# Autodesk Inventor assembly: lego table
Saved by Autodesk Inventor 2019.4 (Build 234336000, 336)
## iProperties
Created: 2020-09
Part Number: lego table
Document SubType Name: Assembly
Designer: Administrator
Title: lego table v49
Author: Administrator
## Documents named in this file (20)
- c:\worker\convert-fusion-r07\tmp\job-1\164\output\files\c50c4620-2026-4653-9277-f8972be5ac5a\c5b1a24b-4982-40ab-9d19-aea12fee247f.iam
- c:\worker\convert-fusion-r07\tmp\job-1\164\output\files\c50c4620-2026-4653-9277-f8972be5ac5a\back.ipt
- c:\worker\convert-fusion-r07\tmp\job-1\164\output\files\c50c4620-2026-4653-9277-f8972be5ac5a\side.ipt
- c:\worker\convert-fusion-r07\tmp\job-1\164\output\files\c50c4620-2026-4653-9277-f8972be5ac5a\front.ipt
- c:\worker\convert-fusion-r07\tmp\job-1\164\output\files\c50c4620-2026-4653-9277-f8972be5ac5a\front trim.ipt
- c:\worker\convert-fusion-r07\tmp\job-1\164\output\files\c50c4620-2026-4653-9277-f8972be5ac5a\bottom insert.ipt
- c:\worker\convert-fusion-r07\tmp\job-1\164\output\files\c50c4620-2026-4653-9277-f8972be5ac5a\rail support.ipt
- c:\worker\convert-fusion-r07\tmp\job-1\164\output\files\c50c4620-2026-4653-9277-f8972be5ac5a\leg.iam
- c:\worker\convert-fusion-r07\tmp\job-1\164\output\files\c50c4620-2026-4653-9277-f8972be5ac5a\leg_1.iam
- c:\worker\convert-fusion-r07\tmp\job-1\164\output\files\c50c4620-2026-4653-9277-f8972be5ac5a\leg_2.iam
- c:\worker\convert-fusion-r07\tmp\job-1\164\output\files\c50c4620-2026-4653-9277-f8972be5ac5a\leg_3.iam
- c:\worker\convert-fusion-r07\tmp\job-1\164\output\files\c50c4620-2026-4653-9277-f8972be5ac5a\roller shelf v31.iam
- c:\worker\convert-fusion-r07\tmp\job-1\164\output\files\c50c4620-2026-4653-9277-f8972be5ac5a\base stiffener.ipt
- c:\worker\convert-fusion-r07\tmp\job-1\164\output\files\c50c4620-2026-4653-9277-f8972be5ac5a\divider.ipt
- c:\worker\convert-fusion-r07\tmp\job-1\164\output\files\c50c4620-2026-4653-9277-f8972be5ac5a\shelf leg a.ipt
- c:\worker\convert-fusion-r07\tmp\job-1\164\output\files\c50c4620-2026-4653-9277-f8972be5ac5a\shelf leg b.ipt
- c:\worker\convert-fusion-r07\tmp\job-1\164\output\files\c50c4620-2026-4653-9277-f8972be5ac5a\shelf.ipt
- c:\worker\convert-fusion-r07\tmp\job-1\164\output\files\c50c4620-2026-4653-9277-f8972be5ac5a\shelf trim.ipt
- c:\worker\convert-fusion-r07\tmp\job-1\164\output\files\c50c4620-2026-4653-9277-f8972be5ac5a\shelf backing.ipt
- c:\worker\convert-fusion-r07\tmp\job-1\164\output\files\c50c4620-2026-4653-9277-f8972be5ac5a\shelf rear support.ipt
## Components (27 placed, 16 different names)
1. back:1
2. side:1
3. side:2
4. front:1
5. front trim:1
6. bottom insert:1
7. rail support:1
8. rail support:2
9. leg:1 [sub-assembly]
10. leg:2 [sub-assembly]
11. leg:3 [sub-assembly]
12. leg:4 [sub-assembly]
13. roller shelf v31:1 [sub-assembly]
14. base stiffener:1
15. base stiffener:2
16. base stiffener:3
17. base stiffener:4
18. base stiffener:5
19. divider:1
20. divider:2
21. divider:3
22. shelf leg a:1
23. shelf leg b:1
24. shelf:1
25. shelf trim:1
26. shelf backing:1
27. shelf rear support:1
